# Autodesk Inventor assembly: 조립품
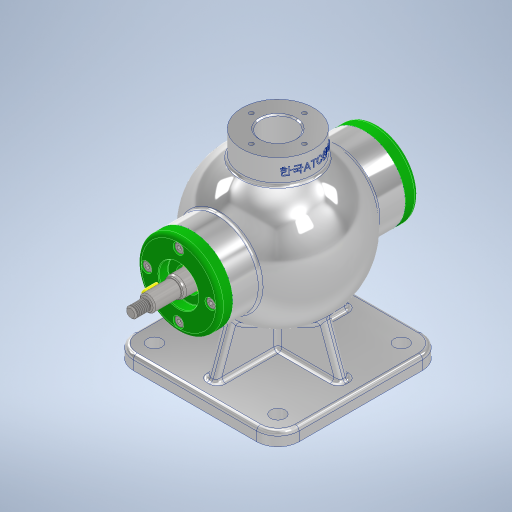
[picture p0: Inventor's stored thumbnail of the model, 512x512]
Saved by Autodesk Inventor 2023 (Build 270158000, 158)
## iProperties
Created: 2023-07
Part Number: 조립품
Document SubType Name: Assembly
Designer: Owner
Author: Owner
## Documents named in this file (10)
- C:\Users\Owner\Desktop\730711V1002\조립품.iam
- C:\Users\Owner\Desktop\730711V1002\본체.ipt
- C:\Users\Owner\Desktop\730711V1002\뒤커버.ipt
- C:\Users\Owner\Desktop\730711V1002\앞커버.ipt
- C:\Users\Owner\Desktop\730711V1002\베어링- 6202.ipt
- KS B 2023 - 6202 - 15 x 35 x 11 - 7.8.ipt
- C:\Users\Owner\Desktop\730711V1002\칼라.ipt
- C:\Users\Owner\Desktop\730711V1002\편심축.ipt
- C:\Users\Owner\Desktop\730711V1002\키 4 x 4 x 12.ipt
- C:\Users\Owner\Desktop\730711V1002\볼트 M4 x 16.ipt
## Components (10 placed, 2 different names)
1. KS B 2023 - 6202 - 15 x 35 x 11 - 7.8:4
2. KS B 2023 - 6202 - 15 x 35 x 11 - 7.8:5
3. ISO 4762 M4 x 16:1
4. ISO 4762 M4 x 16:2
5. ISO 4762 M4 x 16:3
6. ISO 4762 M4 x 16:4
7. ISO 4762 M4 x 16:5
8. ISO 4762 M4 x 16:6
9. ISO 4762 M4 x 16:7
10. ISO 4762 M4 x 16:8
